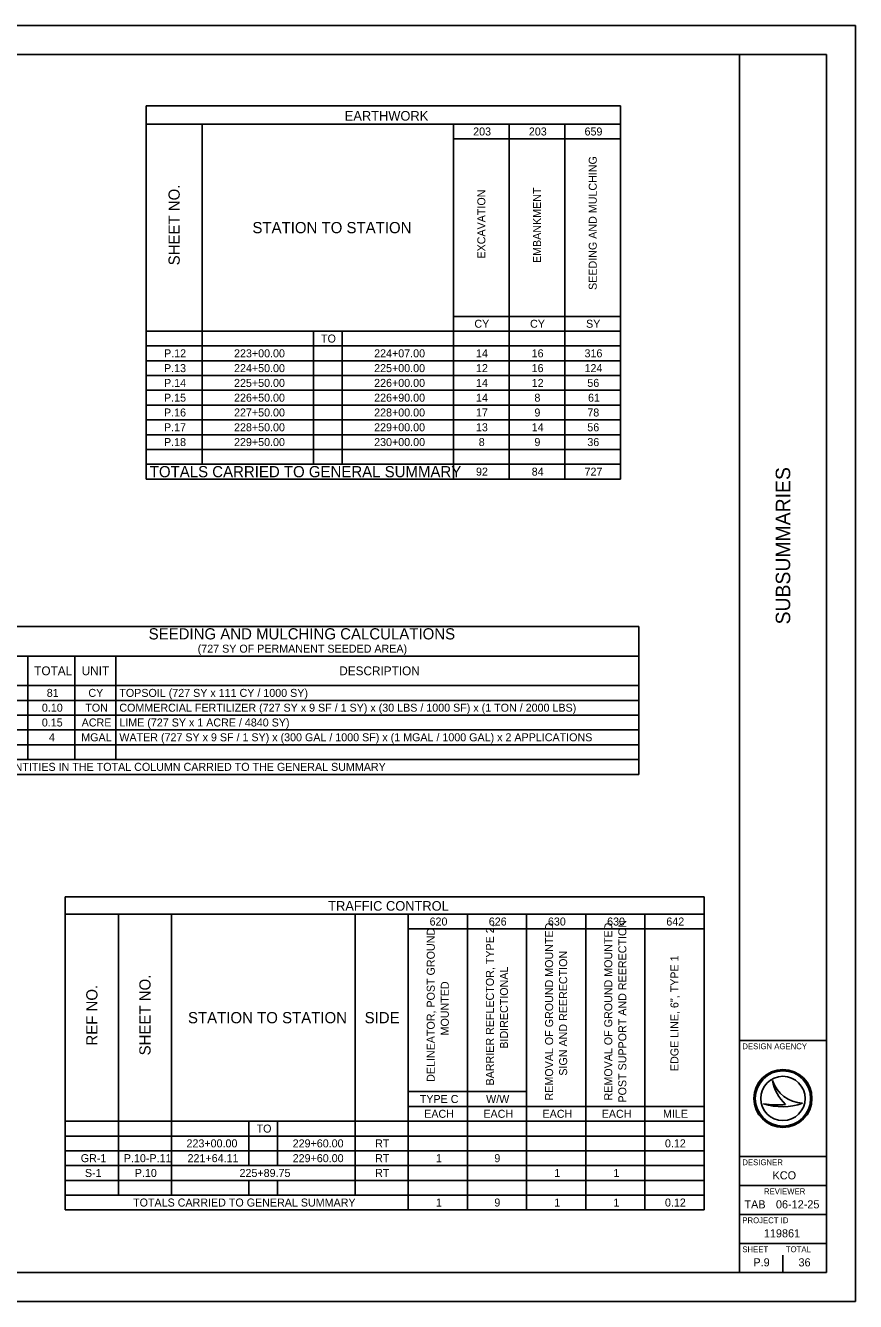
# Model space of a CAD drawing. Extents: x 0 to 34, y 0 to 22.
# Drawn here: x 19.69 to 34, y 0 to 22 of the extents above; entities that cross this region are included whole.
import ezdxf

# ---------------------------------------------------------------- set-up
doc = ezdxf.new("R2010")
doc.units = 0
for name, color, linetype in [('SH_Border', 7, 'Continuous'), ('SH_Cut_Line', 7, 'Continuous'), ('SH_Data', 7, 'Continuous'), ('SH_Text', 7, 'Continuous')]:
    doc.layers.add(name, color=color, linetype=linetype)

msp = doc.modelspace()

# ---------------------------------------------------------------- linework, layer by layer
at = {"layer": 'SH_Border'}
for p, q in [((32, 0.5), (32, 21.5)), ((32, 4.5), (33.5, 4.5)), ((32, 2.5), (33.5, 2.5)), ((32, 2), (33.5, 2)), ((32, 1.5), (33.5, 1.5)), ((32, 1), (33.5, 1))]:
    msp.add_line(p, q, dxfattribs=at)
msp.add_lwpolyline([(1.5, 21.5), (33.5, 21.5), (33.5, 0.5), (1.5, 0.5)], close=True, dxfattribs=at)
at = {"layer": 'SH_Cut_Line'}
msp.add_lwpolyline([(0, 0), (34, 0), (34, 22), (0, 22)], close=True, dxfattribs=at)
at = {"layer": 'SH_Data'}
for p, q in [((32.567, 3.81), (32.567, 3.81)), ((32.417, 3.41), (32.417, 3.41)), ((32.75, 3.5), (32.75, 3.5)), ((33.087, 3.419), (33.087, 3.419)), ((32.375, 0.675), (32.375, 0.675)), ((32.75, 0.5), (32.75, 0.8))]:
    msp.add_line(p, q, dxfattribs=at)
for radius in [0.5, 0.477, 0.477, 0.382]:
    msp.add_circle((32.75, 3.5), radius, dxfattribs=at)
for centre, radius, start, end in [((33.116, 3.998), 0.58, 198.9257, 198.9319), ((33.347, 3.97), 0.796, 191.6379, 191.6421), ((33.116, 3.998), 0.58, 198.9319, 267.1657), ((33.347, 3.97), 0.796, 191.6421, 226.0947), ((32.739, 4.37), 1.013, 251.4576, 290.0832), ((32.648, 4.654), 1.266, 259.4964, 259.4995), ((32.739, 4.37), 1.013, 251.4527, 251.4576), ((32.648, 4.654), 1.266, 259.4995, 276.6672)]:
    msp.add_arc(centre, radius, start, end, dxfattribs=at)
at = {"layer": 'SH_Text'}
for p, q in [((21.776, 20.615), (29.951, 20.615)), ((21.776, 20.615), (21.776, 14.18)), ((29.951, 20.615), (29.951, 14.18)), ((21.776, 20.3), (29.951, 20.3)), ((22.736, 20.3), (22.736, 14.435)), ((27.071, 20.3), (27.071, 14.18)), ((28.031, 20.3), (28.031, 14.18)), ((28.991, 20.3), (28.991, 14.18)), ((27.071, 20.045), (29.951, 20.045)), ((27.071, 16.985), (29.951, 16.985)), ((21.776, 16.73), (29.951, 16.73)), ((24.656, 16.73), (24.656, 14.435)), ((25.151, 16.73), (25.151, 14.435)), ((21.776, 16.475), (29.951, 16.475)), ((21.776, 16.22), (29.951, 16.22)), ((21.776, 15.965), (29.951, 15.965)), ((21.776, 15.71), (29.951, 15.71)), ((21.776, 15.455), (29.951, 15.455)), ((21.776, 15.2), (29.951, 15.2)), ((21.776, 14.945), (29.951, 14.945)), ((21.776, 14.69), (29.951, 14.69)), ((21.776, 14.435), (29.951, 14.435)), ((21.776, 14.18), (29.951, 14.18)), ((18.431, 11.639), (30.266, 11.639)), ((30.266, 11.639), (30.266, 9.089)), ((18.431, 11.129), (30.266, 11.129)), ((19.736, 11.129), (19.736, 9.344)), ((20.546, 11.129), (20.546, 9.344)), ((21.251, 11.129), (21.251, 9.344)), ((18.431, 10.619), (30.266, 10.619)), ((18.431, 10.364), (30.266, 10.364)), ((18.431, 10.109), (30.266, 10.109)), ((18.431, 9.854), (30.266, 9.854)), ((18.431, 9.599), (30.266, 9.599)), ((18.431, 9.344), (30.266, 9.344)), ((18.431, 9.089), (30.266, 9.089)), ((20.38, 6.978), (31.39, 6.978)), ((20.38, 6.978), (20.38, 1.578)), ((31.39, 6.978), (31.39, 1.578)), ((20.38, 6.678), (31.39, 6.678)), ((21.295, 6.678), (21.295, 1.833)), ((22.21, 6.678), (22.21, 1.833)), ((25.375, 6.678), (25.375, 1.833)), ((26.29, 6.678), (26.29, 1.578)), ((27.31, 6.678), (27.31, 1.578)), ((28.33, 6.678), (28.33, 1.578)), ((29.35, 6.678), (29.35, 1.578)), ((30.37, 6.678), (30.37, 1.578)), ((26.29, 6.423), (31.39, 6.423)), ((26.29, 3.618), (28.33, 3.618)), ((26.29, 3.363), (31.39, 3.363)), ((20.38, 3.108), (31.39, 3.108)), ((23.545, 3.108), (23.545, 2.343)), ((24.04, 3.108), (24.04, 2.343)), ((20.38, 2.853), (31.39, 2.853)), ((20.38, 2.598), (31.39, 2.598)), ((20.38, 2.343), (31.39, 2.343)), ((20.38, 2.088), (31.39, 2.088)), ((23.545, 2.088), (23.545, 1.833)), ((24.04, 2.088), (24.04, 1.833)), ((20.38, 1.833), (31.39, 1.833)), ((20.38, 1.578), (31.39, 1.578))]:
    msp.add_line(p, q, dxfattribs=at)
msp.add_lwpolyline([(21.776, 20.615), (21.776, 20.615), (21.776, 20.36), (21.776, 20.36)], close=True, dxfattribs=at)
msp.add_lwpolyline([(21.776, 20.615), (21.776, 20.615), (21.776, 20.36), (21.776, 20.36)], close=True, dxfattribs=at)
msp.add_lwpolyline([(21.776, 20.615), (21.776, 20.615), (21.776, 20.36), (21.776, 20.36)], close=True, dxfattribs=at)
msp.add_lwpolyline([(21.776, 20.615), (21.776, 20.615), (21.776, 20.36), (21.776, 20.36)], close=True, dxfattribs=at)
msp.add_lwpolyline([(21.776, 20.615), (21.776, 20.615), (21.776, 20.36), (21.776, 20.36)], close=True, dxfattribs=at)
msp.add_lwpolyline([(21.776, 20.615), (21.776, 20.615), (21.776, 20.36), (21.776, 20.36)], close=True, dxfattribs=at)
msp.add_lwpolyline([(21.776, 20.615), (21.776, 20.615), (21.776, 20.36), (21.776, 20.36)], close=True, dxfattribs=at)
msp.add_lwpolyline([(21.776, 20.615), (21.776, 20.615), (21.776, 20.36), (21.776, 20.36)], close=True, dxfattribs=at)
msp.add_lwpolyline([(21.776, 20.615), (21.776, 20.615), (21.776, 20.36), (21.776, 20.36)], close=True, dxfattribs=at)

# ---------------------------------------------------------------- texts
at = {"layer": 'SH_Data'}
msp.add_text('SUBSUMMARIES', height=0.25, rotation=90, dxfattribs=at).set_placement((32.875, 11.674))
for s, height, p in [('DESIGN AGENCY', 0.1, (32.05, 4.35)), ('DESIGNER', 0.1, (32.05, 2.35)), ('KCO', 0.14, (32.571, 2.105)), ('REVIEWER', 0.1, (32.422, 1.85)), ('TAB', 0.14, (32.086, 1.605)), ('06-12-25', 0.14, (32.629, 1.605)), ('PROJECT ID', 0.1, (32.05, 1.35)), ('119861', 0.14, (32.421, 1.105)), ('SHEET', 0.1, (32.05, 0.85)), ('TOTAL', 0.1, (32.8, 0.85)), ('P.9', 0.14, (32.24, 0.605)), ('36', 0.14, (33.018, 0.605))]:
    msp.add_text(s, height=height, dxfattribs=at).set_placement(p)
at = {"layer": 'SH_Text'}
for s, height, p in [('EARTHWORK', 0.1656, (25.197, 20.36)), ('203', 0.138, (27.41, 20.104)), ('203', 0.138, (28.37, 20.104)), ('659', 0.138, (29.33, 20.104)), ('STATION TO STATION', 0.1932, (23.605, 18.419)), ('CY', 0.138, (27.431, 16.789)), ('CY', 0.138, (28.391, 16.789)), ('SY', 0.138, (29.356, 16.789)), ('TO', 0.138, (24.788, 16.534)), ('P.12', 0.138, (22.082, 16.279)), ('223+00.00', 0.138, (23.288, 16.279)), ('224+07.00', 0.138, (25.703, 16.279)), ('14', 0.138, (27.459, 16.279)), ('16', 0.138, (28.418, 16.279)), ('316', 0.138, (29.33, 16.279)), ('P.13', 0.138, (22.081, 16.024)), ('224+50.00', 0.138, (23.288, 16.024)), ('225+00.00', 0.138, (25.703, 16.024)), ('12', 0.138, (27.459, 16.024)), ('16', 0.138, (28.418, 16.024)), ('124', 0.138, (29.33, 16.024)), ('P.14', 0.138, (22.082, 15.769)), ('225+50.00', 0.138, (23.288, 15.769)), ('226+00.00', 0.138, (25.703, 15.769)), ('14', 0.138, (27.459, 15.769)), ('12', 0.138, (28.419, 15.769)), ('56', 0.138, (29.378, 15.769)), ('P.15', 0.138, (22.081, 15.514)), ('226+50.00', 0.138, (23.288, 15.514)), ('226+90.00', 0.138, (25.703, 15.514)), ('14', 0.138, (27.459, 15.514)), ('8', 0.138, (28.466, 15.514)), ('61', 0.138, (29.39, 15.514)), ('P.16', 0.138, (22.081, 15.259)), ('227+50.00', 0.138, (23.288, 15.259)), ('228+00.00', 0.138, (25.703, 15.259)), ('17', 0.138, (27.458, 15.259)), ('9', 0.138, (28.466, 15.259)), ('78', 0.138, (29.378, 15.259)), ('P.17', 0.138, (22.081, 15.004)), ('228+50.00', 0.138, (23.288, 15.004)), ('229+00.00', 0.138, (25.703, 15.004)), ('13', 0.138, (27.458, 15.004)), ('14', 0.138, (28.419, 15.004)), ('56', 0.138, (29.378, 15.004)), ('P.18', 0.138, (22.081, 14.749)), ('229+50.00', 0.138, (23.288, 14.749)), ('230+00.00', 0.138, (25.703, 14.749)), ('8', 0.138, (27.506, 14.749)), ('9', 0.138, (28.466, 14.749)), ('36', 0.138, (29.378, 14.749)), ('TOTALS CARRIED TO GENERAL SUMMARY', 0.1932, (21.836, 14.211)), ('92', 0.138, (27.459, 14.239)), ('84', 0.138, (28.419, 14.239)), ('727', 0.138, (29.33, 14.239)), ('SEEDING AND MULCHING CALCULATIONS', 0.1932, (21.816, 11.415)), ('(727 SY OF PERMANENT SEEDED AREA)', 0.138, (22.662, 11.187)), ('TOTAL', 0.1518, (19.844, 10.798)), ('UNIT', 0.1518, (20.662, 10.798)), ('DESCRIPTION', 0.1518, (25.102, 10.798)), ('81', 0.138, (20.06, 10.424)), ('CY', 0.138, (20.778, 10.424)), ('TOPSOIL (727 SY x 111 CY / 1000 SY)', 0.138, (21.311, 10.424)), ('0.10', 0.138, (19.976, 10.169)), ('TON', 0.138, (20.724, 10.169)), ('COMMERCIAL FERTILIZER (727 SY x 9 SF / 1 SY) x (30 LBS / 1000 SF) x (1 TON / 2000 LBS)', 0.138, (21.311, 10.169)), ('0.15', 0.138, (19.975, 9.914)), ('ACRE', 0.138, (20.662, 9.914)), ('LIME (727 SY x 1 ACRE / 4840 SY)', 0.138, (21.311, 9.914)), ('4', 0.138, (20.097, 9.659)), ('MGAL', 0.138, (20.655, 9.659)), ('WATER (727 SY x 9 SF / 1 SY) x (300 GAL / 1000 SF) x (1 MGAL / 1000 GAL) x 2 APPLICATIONS', 0.138, (21.311, 9.659)), ('NOTE: QUANTITIES IN THE TOTAL COLUMN CARRIED TO THE GENERAL SUMMARY', 0.138, (18.491, 9.149)), ('TRAFFIC CONTROL', 0.1656, (24.911, 6.738)), ('620', 0.138, (26.659, 6.482)), ('626', 0.138, (27.679, 6.482)), ('630', 0.138, (28.699, 6.482)), ('630', 0.138, (29.719, 6.482)), ('642', 0.138, (30.74, 6.482)), ('STATION TO STATION', 0.1932, (22.494, 4.797)), ('SIDE', 0.1932, (25.539, 4.797)), ('TYPE C', 0.138, (26.49, 3.422)), ('W/W', 0.138, (27.633, 3.422)), ('EACH', 0.138, (26.566, 3.167)), ('EACH', 0.138, (27.586, 3.167)), ('EACH', 0.138, (28.606, 3.167)), ('EACH', 0.138, (29.626, 3.167)), ('MILE', 0.138, (30.682, 3.167)), ('TO', 0.138, (23.677, 2.912)), ('223+00.00', 0.138, (22.469, 2.657)), ('229+60.00', 0.138, (24.299, 2.657)), ('RT', 0.138, (25.72, 2.657)), ('0.12', 0.138, (30.716, 2.657)), ('GR-1', 0.138, (20.646, 2.402)), ('P.10-P.11', 0.138, (21.389, 2.402)), ('221+64.11', 0.138, (22.487, 2.402)), ('229+60.00', 0.138, (24.299, 2.402)), ('RT', 0.138, (25.72, 2.402)), ('1', 0.138, (26.768, 2.402)), ('9', 0.138, (27.775, 2.402)), ('S-1', 0.138, (20.718, 2.147)), ('P.10', 0.138, (21.578, 2.147)), ('225+89.75', 0.138, (23.383, 2.147)), ('RT', 0.138, (25.72, 2.147)), ('1', 0.138, (28.808, 2.147)), ('1', 0.138, (29.828, 2.147)), ('TOTALS CARRIED TO GENERAL SUMMARY', 0.138, (21.548, 1.637)), ('1', 0.138, (26.768, 1.637)), ('9', 0.138, (27.775, 1.637)), ('1', 0.138, (28.808, 1.637)), ('1', 0.138, (29.828, 1.637)), ('0.12', 0.138, (30.716, 1.637))]:
    msp.add_text(s, height=height, dxfattribs=at).set_placement(p)
for s, height, p in [('SEEDING AND MULCHING', 0.138, (29.54, 17.441)), ('SHEET NO.', 0.1932, (22.352, 17.865)), ('EXCAVATION', 0.138, (27.62, 17.982)), ('EMBANKMENT', 0.138, (28.58, 17.905)), ('DELINEATOR, POST GROUND ', 0.138, (26.748, 3.786)), ('BARRIER REFLECTOR, TYPE 2, ', 0.138, (27.768, 3.724)), ('REMOVAL OF GROUND MOUNTED ', 0.138, (28.788, 3.466)), ('REMOVAL OF GROUND MOUNTED ', 0.138, (29.808, 3.466)), ('POST SUPPORT AND REERECTION', 0.138, (30.05, 3.43)), ('SIGN AND REERECTION', 0.138, (29.03, 3.893)), ('EDGE LINE, 6", TYPE 1', 0.138, (30.949, 3.972)), ('BIDIRECTIONAL', 0.138, (28.01, 4.359)), ('SHEET NO.', 0.1932, (21.849, 4.243)), ('MOUNTED', 0.138, (26.99, 4.587)), ('REF NO.', 0.1932, (20.934, 4.412))]:
    msp.add_text(s, height=height, rotation=90, dxfattribs=at).set_placement(p)

doc.saveas('drawing.dxf')
